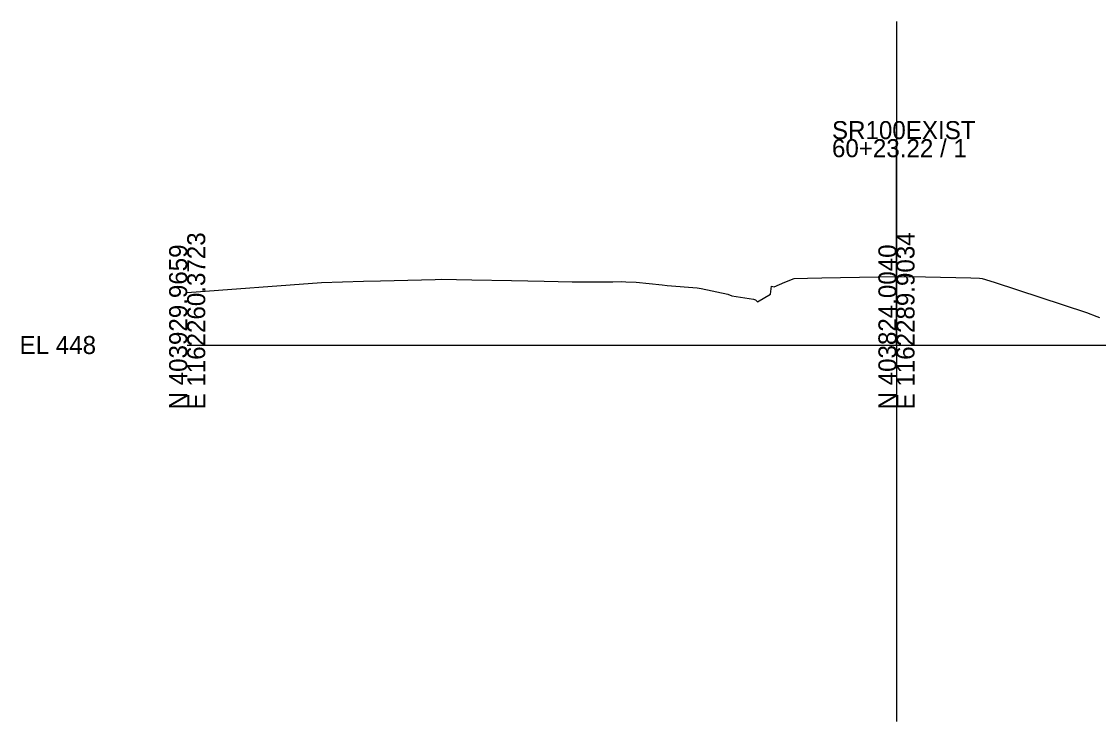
# Model space of a CAD drawing. Extents: x 37 to 1710, y 707 to 2305.
# Drawn here: x 629.4 to 796.4, y 1337.8 to 1446.4 of the extents above; entities that cross this region are included whole.
import ezdxf

# ---------------------------------------------------------------- set-up
doc = ezdxf.new("R2010")
doc.units = 0
for name, color, linetype in [('DESIGN - SHEET - Light Grid', 7, 'Continuous'), ('DESIGN - SHEET - Linework', 7, 'Continuous'), ('SURVEY - GROUND - Top of Ground', 7, 'Continuous')]:
    doc.layers.add(name, color=color, linetype=linetype)

msp = doc.modelspace()

# ---------------------------------------------------------------- linework, layer by layer
at = {"layer": 'DESIGN - SHEET - Light Grid'}
for p, q in [((765.09, 1396.22), (765.09, 1428.17)), ((655.09, 1396.22), (765.09, 1396.22)), ((765.09, 1396.22), (875.09, 1396.22))]:
    msp.add_line(p, q, dxfattribs=at)
at = {"layer": 'DESIGN - SHEET - Linework'}
msp.add_line((765.09, 1446.43), (765.09, 1337.79), dxfattribs=at)
at = {"layer": 'SURVEY - GROUND - Top of Ground'}
msp.add_lwpolyline([(655.09, 1404.36), (675.92, 1405.92), (682.45, 1406.14), (685.07, 1406.2), (693.55, 1406.39), (694.59, 1406.42), (696.88, 1406.39), (699.23, 1406.33), (705.37, 1406.21), (710.48, 1406.11), (714.81, 1406.03), (719.35, 1406.04), (721.12, 1406.02), (722.47, 1406.09), (723.11, 1406.03), (724.74, 1405.99), (728.74, 1405.56), (729.51, 1405.46), (734.17, 1405.11), (734.8, 1404.98), (738.92, 1404.13), (739.58, 1403.85), (742.91, 1403.31), (743.24, 1403.25), (743.53, 1402.93), (745.57, 1404.13), (745.7, 1405.36), (746.14, 1405.26), (747.8, 1405.99), (749.22, 1406.54), (751.28, 1406.59), (753.53, 1406.65), (762.24, 1406.82), (765.14, 1406.87), (769.6, 1406.79), (776.6, 1406.67), (777.97, 1406.59), (778.37, 1406.56), (780.22, 1405.98), (794.58, 1401.28), (796.15, 1400.66), (796.6, 1400.47)], dxfattribs=at)

# ---------------------------------------------------------------- texts
at = {"layer": 'DESIGN - SHEET - Light Grid'}
for s, p in [('SR100EXIST', (755.09, 1428.17)), ('60+23.22 / 1', (755.09, 1425.37)), ('EL 448', (629.09, 1394.82))]:
    msp.add_text(s, height=2.8, dxfattribs=at).set_placement(p)
for s, p in [('E 1162260.3723', (657.89, 1386.22)), ('E 1162289.9034', (767.89, 1386.22)), ('N 403929.9659', (655.09, 1386.22)), ('N 403824.0040', (765.09, 1386.22))]:
    msp.add_text(s, height=2.8, rotation=90, dxfattribs=at).set_placement(p)

doc.saveas('drawing.dxf')
